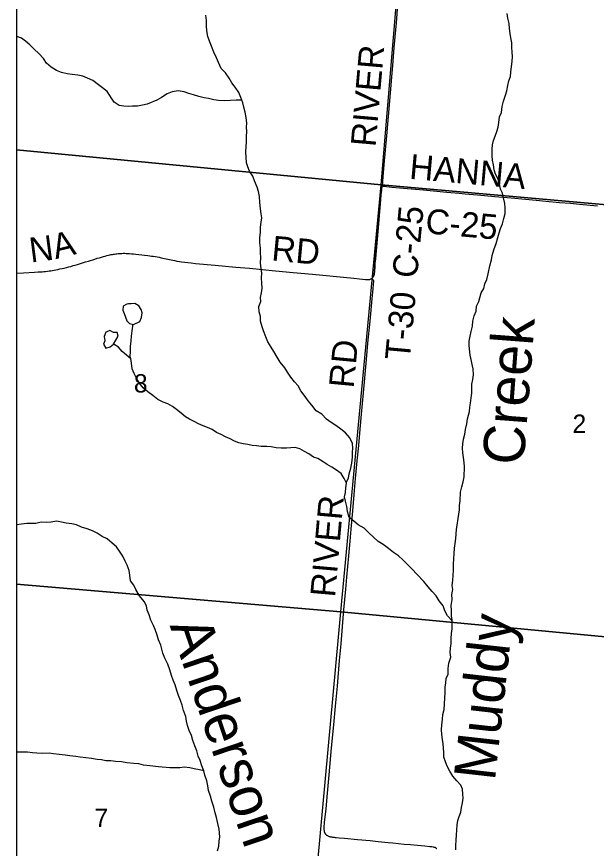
# Model space of a CAD drawing. Extents: x 0 to 1067, y 0 to 440.
# Drawn here: x 798.04 to 799.365, y 354.272 to 356.173 of the extents above; entities that cross this region are included whole.
import ezdxf

# ---------------------------------------------------------------- set-up
doc = ezdxf.new("R2010")
doc.units = 0
for name, color, linetype in [('GM_X_County_Road', 7, 'Continuous'), ('GM_X_County_Road_Text', 7, 'Continuous'), ('GM_X_Minor_Lake', 7, 'Continuous'), ('GM_X_Minor_River', 7, 'Continuous'), ('GM_X_Minor_River_Text', 7, 'Continuous'), ('GM_X_Section', 7, 'Continuous'), ('GM_X_Section_Text', 7, 'Continuous'), ('GM_X_Township_Road', 7, 'Continuous'), ('GM_X_Township_Road_Text', 7, 'Continuous'), ('GM_X_US_Shield', 7, 'Continuous')]:
    doc.layers.add(name, color=color, linetype=linetype)

msp = doc.modelspace()

# ---------------------------------------------------------------- linework, layer by layer
at = {"layer": 'GM_X_County_Road'}
for points in [[(798.8515, 355.575), (798.8522, 355.5755), (798.853, 355.5763), (798.8536, 355.577), (798.8541, 355.5777), (798.8551, 355.5792), (798.8556, 355.5803), (798.8561, 355.5812), (798.8563, 355.582), (798.8566, 355.583), (798.8567, 355.5838), (798.857, 355.5855), (798.8573, 355.5872), (798.8575, 355.5889), (798.8577, 355.5911), (798.8579, 355.5936), (798.8582, 355.5992), (798.8588, 355.6098), (798.8597, 355.6193), (798.8621, 355.6472), (798.8669, 355.6994), (798.8696, 355.7367), (798.8712, 355.7547), (798.8723, 355.7671), (798.8726, 355.7697), (798.873, 355.7724), (798.8734, 355.7749), (798.874, 355.7797), (798.8744, 355.7827), (798.875, 355.7863)], [(798.875, 355.7863), (798.8776, 355.786), (798.8807, 355.7856), (798.885, 355.7851), (798.8973, 355.7837), (798.915, 355.7819), (798.9699, 355.777), (799.0004, 355.7742), (799.0228, 355.7722), (799.0513, 355.7697), (799.0651, 355.7685), (799.0934, 355.766), (799.1327, 355.7623), (799.1698, 355.7588), (799.2026, 355.7558), (799.2271, 355.7536), (799.2495, 355.7515), (799.2805, 355.7487), (799.3052, 355.7465), (799.3263, 355.7445), (799.3669, 355.7409)], [(798.0401, 355.587), (798.0558, 355.5879), (798.0811, 355.5891), (798.0895, 355.5896), (798.0938, 355.5899), (798.0983, 355.5903), (798.1023, 355.5906), (798.1062, 355.591), (798.1107, 355.5915), (798.1145, 355.592), (798.1183, 355.5926), (798.1255, 355.5938), (798.1298, 355.5946), (798.134, 355.5954), (798.1391, 355.5965), (798.1438, 355.5976), (798.1487, 355.5987), (798.1542, 355.6001), (798.1594, 355.6015), (798.1637, 355.6025), (798.1693, 355.6041), (798.1739, 355.6054), (798.1788, 355.6068), (798.184, 355.6083), (798.1909, 355.6105), (798.1978, 355.6125), (798.2043, 355.6145), (798.2185, 355.6191), (798.224, 355.6208), (798.2293, 355.6223), (798.2337, 355.6236), (798.2382, 355.625), (798.2422, 355.6261), (798.2464, 355.6272), (798.2501, 355.628), (798.2527, 355.6286), (798.2556, 355.6292), (798.2588, 355.6298), (798.2612, 355.6302), (798.2637, 355.6306), (798.2666, 355.631), (798.2691, 355.6314), (798.2723, 355.6317), (798.2772, 355.632), (798.2806, 355.6322), (798.2839, 355.6323), (798.2875, 355.6323), (798.2907, 355.6322), (798.2945, 355.632), (798.2981, 355.6317), (798.3026, 355.6314), (798.3069, 355.631), (798.3121, 355.6306), (798.3194, 355.6298), (798.3262, 355.629), (798.3323, 355.6283), (798.3401, 355.6273), (798.3445, 355.6266), (798.348, 355.6261), (798.3524, 355.6255), (798.3571, 355.6247), (798.3614, 355.624), (798.3661, 355.6231), (798.3704, 355.6222), (798.393, 355.6172), (798.3972, 355.6163), (798.4012, 355.6155), (798.4063, 355.6146), (798.4119, 355.6136), (798.4171, 355.6129), (798.4242, 355.6119), (798.4311, 355.6111), (798.439, 355.6103), (798.4488, 355.6093), (798.494, 355.6052), (798.5411, 355.6008), (798.5724, 355.598), (798.6317, 355.5922), (798.6722, 355.5884), (798.7162, 355.5843), (798.7868, 355.5775), (798.8103, 355.5753), (798.8238, 355.5739), (798.8368, 355.5724), (798.8398, 355.5721), (798.8418, 355.5721), (798.8434, 355.5721), (798.8448, 355.5722), (798.8458, 355.5724), (798.847, 355.5727), (798.848, 355.573), (798.8488, 355.5734), (798.8496, 355.5738), (798.8505, 355.5744), (798.8515, 355.575)]]:
    msp.add_lwpolyline(points, dxfattribs=at)
at = {"layer": 'GM_X_Minor_Lake'}
for points in [[(798.2958, 355.5165), (798.2922, 355.5162), (798.2838, 355.5114), (798.2829, 355.5024), (798.2858, 355.4947), (798.2891, 355.486), (798.2916, 355.478), (798.2983, 355.4718), (798.307, 355.4698)], [(798.307, 355.4698), (798.3218, 355.4767), (798.3257, 355.4858), (798.3267, 355.496), (798.3245, 355.504), (798.319, 355.5124), (798.31, 355.5175), (798.3016, 355.5168), (798.2958, 355.5165)], [(798.2459, 355.4528), (798.2439, 355.4518), (798.2404, 355.4424), (798.2413, 355.4325), (798.2382, 355.4243), (798.2441, 355.4158), (798.2536, 355.4183), (798.2613, 355.425)], [(798.2613, 355.425), (798.2718, 355.443), (798.2696, 355.4514), (798.2617, 355.4515), (798.2531, 355.4562), (798.2459, 355.4528)]]:
    msp.add_lwpolyline(points, dxfattribs=at)
at = {"layer": 'GM_X_Minor_River'}
for points in [[(798.7927, 355.1085), (798.7983, 355.1185), (798.7997, 355.1283), (798.8035, 355.1415), (798.8058, 355.1529), (798.8073, 355.1662), (798.8076, 355.1776), (798.8083, 355.1871), (798.8071, 355.1978), (798.801, 355.2109), (798.7915, 355.2222), (798.7811, 355.2305), (798.7696, 355.2385), (798.7591, 355.2453), (798.7484, 355.2532), (798.7373, 355.2646), (798.7246, 355.2726), (798.7144, 355.2851), (798.7063, 355.2952), (798.699, 355.3054), (798.6895, 355.3178), (798.683, 355.3291), (798.6746, 355.3388), (798.6669, 355.3493), (798.6589, 355.361), (798.6531, 355.3707), (798.6425, 355.3832), (798.6352, 355.3952), (798.6276, 355.4076), (798.6219, 355.4177), (798.6139, 355.4297), (798.6093, 355.4413), (798.604, 355.4548), (798.6008, 355.4644), (798.5974, 355.4774), (798.597, 355.4877), (798.5946, 355.4988), (798.5935, 355.511), (798.598, 355.5219), (798.5975, 355.5315), (798.5993, 355.5421), (798.6011, 355.5523), (798.6003, 355.5637), (798.5996, 355.5759), (798.6003, 355.5869), (798.5986, 355.5965), (798.5971, 355.6102), (798.5979, 355.6216), (798.5971, 355.6342), (798.597, 355.6441), (798.5954, 355.6559), (798.5958, 355.6685), (798.5969, 355.6795), (798.5976, 355.692), (798.5987, 355.7038), (798.6002, 355.7132), (798.5985, 355.7228), (798.597, 355.7342), (798.5959, 355.7487), (798.5951, 355.7621), (798.5924, 355.7732), (798.5893, 355.7832), (798.5837, 355.7982), (798.5794, 355.8086), (798.5725, 355.8198), (798.5683, 355.8298), (798.5651, 355.8394), (798.5644, 355.852), (798.5636, 355.8634), (798.5647, 355.8763), (798.565, 355.8862), (798.565, 355.8992), (798.5657, 355.9105), (798.5652, 355.9204), (798.5659, 355.9299), (798.5648, 355.9429), (798.5621, 355.9548), (798.559, 355.9666), (798.557, 355.9762), (798.5524, 355.9885), (798.5474, 355.9997), (798.5395, 356.0121), (798.5318, 356.0219), (798.526, 356.0323), (798.5176, 356.0447), (798.5073, 356.0549), (798.5016, 356.0684), (798.497, 356.0788), (798.4906, 356.0923), (798.4853, 356.1054), (798.4811, 356.1173), (798.4768, 356.1277), (798.4749, 356.1407), (798.4738, 356.1525), (798.4737, 356.1647), (798.4726, 356.1769)], [(799.0467, 355.0108), (799.0487, 355.0259), (799.0501, 355.0362), (799.0516, 355.046), (799.0522, 355.0559), (799.0533, 355.0665), (799.0539, 355.0867), (799.0569, 355.0984), (799.0606, 355.1097), (799.0629, 355.1214), (799.0635, 355.1443), (799.0627, 355.1542), (799.0611, 355.1653), (799.0595, 355.176), (799.0587, 355.187), (799.0598, 355.1965), (799.0612, 355.2075), (799.0642, 355.2192), (799.0657, 355.2294), (799.0687, 355.2423), (799.0702, 355.2537), (799.0748, 355.2707), (799.0755, 355.2805), (799.0769, 355.29), (799.0788, 355.3017), (799.0798, 355.3124), (799.0802, 355.3234), (799.0801, 355.3329), (799.0823, 355.3435), (799.0841, 355.3549), (799.083, 355.3682), (799.0806, 355.3778), (799.0787, 355.3897), (799.0763, 355.3993), (799.0739, 355.4214), (799.0742, 355.4313), (799.0761, 355.4426), (799.0787, 355.4536), (799.082, 355.4657), (799.0824, 355.4775), (799.0858, 355.4892), (799.0899, 355.4997), (799.091, 355.5111), (799.0958, 355.5223), (799.1017, 355.5416), (799.1073, 355.552), (799.1095, 355.5623), (799.114, 355.5724), (799.1171, 355.5856), (799.121, 355.6034), (799.1248, 355.6177), (799.1262, 355.6272), (799.13, 355.6404), (799.1358, 355.6547), (799.1396, 355.6686), (799.1429, 355.6792), (799.1455, 355.689), (799.15, 355.6995), (799.1534, 355.7116), (799.1564, 355.7233), (799.1564, 355.7355), (799.1555, 355.7458), (799.1525, 355.7588), (799.1501, 355.7695), (799.1455, 355.7792), (799.1436, 355.7914), (799.1394, 355.8029), (799.1343, 355.813), (799.1312, 355.8233), (799.1293, 355.8348), (799.1273, 355.8448), (799.1268, 355.8547), (799.1265, 355.8703), (799.1276, 355.8801), (799.1298, 355.8899), (799.1335, 355.9001), (799.1372, 355.9106), (799.1405, 355.9204), (799.142, 355.9314), (799.1431, 355.9439), (799.1476, 355.9541), (799.1491, 355.9677), (799.1521, 355.9802), (799.1567, 355.9937), (799.1597, 356.0035), (799.1627, 356.016), (799.1649, 356.0262), (799.1682, 356.0367), (799.1693, 356.0466), (799.1704, 356.0591), (799.1722, 356.0704), (799.173, 356.0822), (799.1721, 356.0917), (799.1717, 356.1028), (799.1712, 356.1134), (799.1693, 356.1245), (799.1673, 356.1345), (799.1661, 356.1459), (799.1657, 356.1577), (799.1623, 356.17), (799.1611, 356.1806)], [(798.5547, 355.9825), (798.542, 355.982), (798.5291, 355.9816), (798.5146, 355.9809), (798.501, 355.9814), (798.4908, 355.9832), (798.4784, 355.9858), (798.4685, 355.9873), (798.4561, 355.9907), (798.4445, 355.9945), (798.4339, 355.9975), (798.4227, 356.0016), (798.409, 356.0036), (798.3957, 356.0013), (798.3838, 355.9964), (798.3714, 355.988), (798.3606, 355.9826), (798.3383, 355.9734), (798.328, 355.9711), (798.3162, 355.9688), (798.3052, 355.9684), (798.2957, 355.9675), (798.2851, 355.9686), (798.2745, 355.9701), (798.2629, 355.978), (798.247, 356.0021), (798.2366, 356.0104), (798.2269, 356.0171), (798.2139, 356.0274), (798.2019, 356.0324), (798.1914, 356.0372), (798.1797, 356.0395), (798.1673, 356.041), (798.1555, 356.0425), (798.1424, 356.0456), (798.1315, 356.0497), (798.1192, 356.0577), (798.1085, 356.0672), (798.1012, 356.0777), (798.0909, 356.089), (798.0802, 356.0988), (798.0702, 356.1086), (798.0606, 356.1173), (798.0509, 356.1241), (798.0404, 356.1278), (798.0401, 356.1278)], [(799.0351, 354.7927), (799.0244, 354.8036), (799.0186, 354.8152), (799.0144, 354.8264), (799.0053, 354.8384), (798.9984, 354.8497), (798.9896, 354.8595), (798.9804, 354.8697), (798.9705, 354.8821), (798.9543, 354.899), (798.9436, 354.9104), (798.9333, 354.921), (798.9226, 354.932), (798.9127, 354.941), (798.9011, 354.9486), (798.8896, 354.9577), (798.8777, 354.9665), (798.8662, 354.9737), (798.8551, 354.9839), (798.8447, 354.9937), (798.834, 355.004), (798.8202, 355.012), (798.8102, 355.0203), (798.7999, 355.0286), (798.7964, 355.042), (798.7945, 355.0539), (798.7915, 355.0658), (798.7895, 355.0761), (798.7917, 355.0859), (798.7923, 355.0962), (798.7934, 355.1068), (798.7888, 355.1173), (798.7812, 355.1289), (798.7711, 355.1364), (798.7603, 355.1432), (798.7499, 355.1497), (798.7402, 355.1557), (798.7283, 355.1636), (798.7185, 355.1666), (798.7077, 355.1738), (798.698, 355.1794), (798.6872, 355.1858), (798.6766, 355.1884), (798.6668, 355.188), (798.6565, 355.1868), (798.6447, 355.1871), (798.633, 355.1879), (798.622, 355.1897), (798.6114, 355.1904), (798.5985, 355.1908), (798.5883, 355.1923), (798.5785, 355.1934), (798.5683, 355.1956), (798.5573, 355.1967), (798.5475, 355.1989), (798.5378, 355.203), (798.5277, 355.2082), (798.5172, 355.2127), (798.5075, 355.218), (798.497, 355.2229), (798.487, 355.2293), (798.4765, 355.2338), (798.4663, 355.2383), (798.4555, 355.2424), (798.4458, 355.2477), (798.4353, 355.2529), (798.4256, 355.2586), (798.416, 355.2669), (798.4056, 355.2755), (798.3959, 355.2819), (798.3858, 355.2879), (798.3746, 355.2921), (798.363, 355.2985), (798.3515, 355.3076), (798.34, 355.3156), (798.3289, 355.3251), (798.3201, 355.3364), (798.3139, 355.3469), (798.3086, 355.3577), (798.3043, 355.3685), (798.3018, 355.3876), (798.2995, 355.3975), (798.3005, 355.407), (798.3001, 355.4192), (798.3016, 355.4321), (798.3027, 355.4427), (798.3042, 355.4548), (798.3056, 355.4655), (798.3053, 355.4704)], [(798.3013, 355.391), (798.2912, 355.3992), (798.2815, 355.4077), (798.273, 355.4178), (798.2633, 355.424), (798.2613, 355.425)], [(798.4342, 354.5415), (798.4308, 354.5534), (798.428, 354.5634), (798.4264, 354.5737), (798.4215, 354.5876), (798.4185, 354.5995), (798.4142, 354.6106), (798.41, 354.6214), (798.4058, 354.6334), (798.402, 354.6457), (798.3974, 354.6568), (798.3939, 354.6672), (798.3905, 354.6807), (798.3855, 354.6934), (798.3787, 354.7073), (798.3745, 354.7188), (798.3693, 354.7365), (798.3644, 354.7492), (798.3609, 354.7592), (798.3564, 354.7723), (798.3525, 354.7819), (798.3471, 354.7939), (798.3429, 354.8058), (798.3387, 354.817), (798.3371, 354.8266), (798.3313, 354.8367), (798.3207, 354.8495), (798.3127, 354.8639), (798.3081, 354.8739), (798.3, 354.8841), (798.2989, 354.897), (798.2969, 354.907), (798.2923, 354.9193), (798.2884, 354.9289), (798.2831, 354.9398), (798.2751, 354.9518), (798.2685, 354.9615), (798.2585, 354.9702), (798.247, 354.9797), (798.2358, 354.9854), (798.2239, 354.9926), (798.2138, 354.9978), (798.201, 355.0028), (798.1883, 355.0066), (798.1766, 355.0115), (798.1661, 355.0138), (798.1536, 355.0153), (798.143, 355.0179), (798.131, 355.0202), (798.1187, 355.0175), (798.1085, 355.017), (798.0964, 355.0178), (798.0841, 355.0151), (798.0743, 355.015), (798.0636, 355.0146), (798.0511, 355.0135), (798.0401, 355.012)], [(799.0437, 354.2688), (799.0436, 354.2795), (799.0443, 354.2905), (799.0451, 354.3034), (799.0457, 354.3137), (799.0465, 354.3262), (799.0479, 354.3357), (799.0508, 354.3455), (799.0549, 354.3553), (799.0564, 354.3659), (799.0589, 354.3765), (799.0604, 354.3867), (799.0599, 354.3963), (799.0587, 354.4073), (799.0552, 354.417), (799.0456, 354.4268), (799.0364, 354.437), (799.0296, 354.449), (799.0234, 354.4602), (799.0196, 354.4702), (799.0161, 354.4806), (799.0164, 354.4916), (799.0152, 354.5016), (799.0147, 354.5115), (799.0131, 354.5214), (799.0112, 354.5329), (799.0107, 354.544), (799.0114, 354.5542), (799.0133, 354.5675), (799.014, 354.5781), (799.0166, 354.5899), (799.0177, 354.6024), (799.0185, 354.6157), (799.0193, 354.6286), (799.0192, 354.6404), (799.0207, 354.6507), (799.0213, 354.6602), (799.0258, 354.6707), (799.0262, 354.6836), (799.0277, 354.6954), (799.0319, 354.7093), (799.0307, 354.72), (799.0317, 354.7295), (799.0328, 354.7409), (799.0327, 354.7516), (799.0338, 354.7637), (799.0353, 354.7743), (799.0352, 354.7842), (799.0351, 354.7937), (799.0339, 354.8041), (799.0338, 354.8159), (799.0327, 354.8277), (799.0353, 354.8409), (799.0342, 354.8528), (799.0364, 354.8638), (799.0355, 354.8733), (799.037, 354.8843), (799.0373, 354.8965), (799.0384, 354.9075), (799.0384, 354.9212), (799.0392, 354.9345), (799.0399, 354.9451), (799.0403, 354.9581), (799.0417, 354.9687), (799.0436, 354.9808), (799.0449, 355.0009), (799.0467, 355.0108)], [(798.4991, 354.2669), (798.5024, 354.2775), (798.5031, 354.2885), (798.5042, 354.2983), (798.5028, 354.3163), (798.5001, 354.3293), (798.4971, 354.3431), (798.494, 354.3535), (798.4906, 354.3662), (798.4864, 354.38), (798.483, 354.3919), (798.4788, 354.4042), (798.4768, 354.4153), (798.4745, 354.4264), (798.4704, 354.4399), (798.468, 354.4495), (798.4634, 354.461), (798.4596, 354.473), (798.4549, 354.4834), (798.4515, 354.4949), (798.4469, 354.5068), (798.4427, 354.5192), (798.44, 354.5299), (798.4342, 354.5415)], [(798.468, 354.4495), (798.4578, 354.4521), (798.4461, 354.4539), (798.4359, 354.4562), (798.4231, 354.4577), (798.4132, 354.4565), (798.4018, 354.4564), (798.39, 354.456), (798.3643, 354.4584), (798.3442, 354.4613), (798.3302, 354.4628), (798.3193, 354.4654), (798.308, 354.4666), (798.2921, 354.4678), (798.28, 354.4697), (798.266, 354.4705), (798.2554, 354.472), (798.244, 354.4723), (798.2338, 354.4745), (798.224, 354.4756), (798.2115, 354.4779), (798.1979, 354.479), (798.1854, 354.4809), (798.1756, 354.482), (798.162, 354.4836), (798.151, 354.4854), (798.137, 354.487), (798.1246, 354.4885), (798.1147, 354.4899), (798.0988, 354.4889), (798.0863, 354.4901), (798.0764, 354.4904), (798.0651, 354.4922), (798.0545, 354.4922), (798.0435, 354.4925), (798.0401, 354.4925)]]:
    msp.add_lwpolyline(points, dxfattribs=at)
at = {"layer": 'GM_X_Section'}
for points in [[(798.9566, 356.7904), (799.9676, 356.6989), (799.8698, 355.7001), (798.8732, 355.7891)], [(798.8732, 355.7891), (799.8698, 355.7001), (799.7802, 354.7186), (798.781, 354.8126)], [(798.781, 354.8126), (799.7802, 354.7186), (799.6925, 353.7106), (798.688, 353.8024)]]:
    msp.add_lwpolyline(points, close=True, dxfattribs=at)
at = {"layer": 'GM_X_Township_Road'}
for points in [[(799.7017, 353.7093), (799.8752, 355.6984), (799.9856, 356.8149), (800.0635, 357.6021), (798.0401, 357.6021), (798.0401, 353.8616)], [(798.9098, 356.1905), (798.9071, 356.159), (798.9022, 356.1026), (798.899, 356.0618), (798.8974, 356.0438), (798.8887, 355.9448), (798.8848, 355.9009), (798.8792, 355.8353), (798.8769, 355.8074), (798.875, 355.7863)], [(798.875, 355.7863), (798.8744, 355.7827), (798.874, 355.7797), (798.8734, 355.7749), (798.873, 355.7724), (798.8726, 355.7697), (798.8723, 355.7671), (798.8712, 355.7547), (798.8696, 355.7367), (798.8669, 355.6994), (798.8621, 355.6472), (798.8597, 355.6193), (798.8588, 355.6098), (798.8582, 355.5992), (798.8579, 355.5936), (798.8577, 355.5911), (798.8575, 355.5889), (798.8573, 355.5872), (798.857, 355.5855), (798.8567, 355.5838), (798.8566, 355.583), (798.8563, 355.582), (798.8561, 355.5812), (798.8556, 355.5803), (798.8551, 355.5792), (798.8541, 355.5777), (798.8536, 355.577), (798.853, 355.5763), (798.8522, 355.5755), (798.8515, 355.575)], [(798.8515, 355.575), (798.8529, 355.5735), (798.8539, 355.5725), (798.8546, 355.5715), (798.8551, 355.5705), (798.8551, 355.5693), (798.8529, 355.5432), (798.8515, 355.5283), (798.8467, 355.4774), (798.8421, 355.4269), (798.8387, 355.3898), (798.8318, 355.3135), (798.8272, 355.2646), (798.8242, 355.2303), (798.8208, 355.1931), (798.8176, 355.1579), (798.8139, 355.1177), (798.8107, 355.0813), (798.8074, 355.0436), (798.8035, 355.0016), (798.8012, 354.9747), (798.7981, 354.9405), (798.7936, 354.8925), (798.7914, 354.8647), (798.7871, 354.8171), (798.784, 354.7794), (798.7807, 354.7399), (798.777, 354.7016), (798.7721, 354.6429), (798.7677, 354.5971), (798.7637, 354.5546), (798.7591, 354.5019), (798.7534, 354.4407), (798.7495, 354.3987), (798.7462, 354.3629), (798.7429, 354.3311), (798.7422, 354.321), (798.7421, 354.3186), (798.7422, 354.316), (798.7422, 354.3147), (798.7424, 354.3132), (798.7425, 354.312), (798.7427, 354.3111), (798.743, 354.3101), (798.7433, 354.3093), (798.7437, 354.3084), (798.7442, 354.3075), (798.7446, 354.3066), (798.7454, 354.3057), (798.7459, 354.305), (798.7465, 354.3043), (798.7473, 354.3036), (798.7484, 354.3027), (798.7492, 354.3022), (798.7503, 354.3015), (798.7514, 354.3009), (798.7526, 354.3003), (798.7542, 354.2997), (798.7556, 354.2993), (798.757, 354.2988), (798.7586, 354.2985), (798.76, 354.2983), (798.7617, 354.298), (798.7635, 354.2978), (798.7655, 354.2976), (798.7679, 354.2974), (798.7702, 354.2971), (798.7771, 354.2966), (798.7889, 354.2956), (798.8188, 354.2927), (798.8476, 354.29), (798.8664, 354.2882), (798.8892, 354.2859), (798.8997, 354.285), (798.9126, 354.2836), (798.9257, 354.2822), (798.9399, 354.2808), (798.9563, 354.2794), (798.9725, 354.2779), (798.9841, 354.2767), (798.989, 354.2762), (798.992, 354.2756), (798.9932, 354.2754), (798.9942, 354.2752), (798.9953, 354.2748), (798.9964, 354.2744), (798.9972, 354.274), (798.9981, 354.2734), (798.9987, 354.2731), (798.9997, 354.2723), (799.0003, 354.2718)]]:
    msp.add_lwpolyline(points, dxfattribs=at)
at = {"layer": 'GM_X_US_Shield'}
for points in [[(798.0401, 356.882), (798.0401, 355.8691), (798.8732, 355.7891), (798.9566, 356.7904)], [(798.0401, 355.8691), (798.0401, 354.8762), (798.781, 354.8126), (798.8732, 355.7891)], [(798.0401, 354.8762), (798.0401, 353.8646), (798.688, 353.8024), (798.781, 354.8126)]]:
    msp.add_lwpolyline(points, close=True, dxfattribs=at)

# ---------------------------------------------------------------- texts
at = {"layer": 'GM_X_County_Road_Text'}
for s, height, rotation, p in [('HANNA', 0.05682, 354.9076, (798.936, 355.8027)), ('C-25', 0.05682, 84.5621, (798.9547, 355.574)), ('C-25', 0.05682, 354.8705, (798.9725, 355.6783)), ('N', 0.0568, 7.3798, (798.0727, 355.611)), ('A', 0.0568, 13.7321, (798.1291, 355.6187)), ('RD', 0.05682, 354.5823, (798.621, 355.6161))]:
    msp.add_text(s, height=height, rotation=rotation, dxfattribs=at).set_placement(p)
at = {"layer": 'GM_X_Minor_River_Text'}
for s, height, rotation, p in [('Creek', 0.09462, 85.6154, (799.1983, 355.1464)), ('Muddy', 0.09464, 83.6168, (799.1327, 354.4249)), ('Anderson', 0.09467, 288.6758, (798.3894, 354.7818))]:
    msp.add_text(s, height=height, rotation=rotation, dxfattribs=at).set_placement(p)
at = {"layer": 'GM_X_Section_Text'}
for s, p in [('8', (798.3081, 355.3141)), ('2', (799.3102, 355.2219)), ('7', (798.2181, 354.3213))]:
    msp.add_text(s, height=0.0419, rotation=0, dxfattribs=at).set_placement(p)
at = {"layer": 'GM_X_Township_Road_Text'}
for s, rotation, p in [('RIVER', 85.0096, (798.86, 355.8743)), ('T-30', 84.7054, (798.9381, 355.3862)), ('RD', 84.5839, (798.81, 355.3228)), ('RIVER', 84.9897, (798.7675, 354.845))]:
    msp.add_text(s, height=0.05682, rotation=rotation, dxfattribs=at).set_placement(p)

doc.saveas('drawing.dxf')
